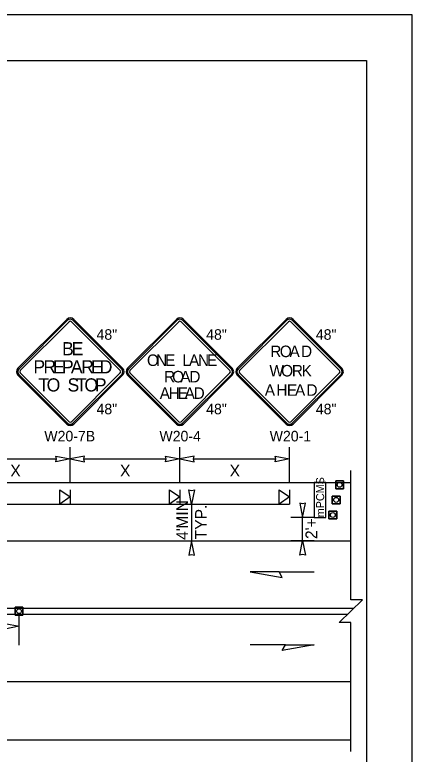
# Model space of a CAD drawing. Extents: x 99999.1 to 100095.7, y 99995 to 100010.7.
# Drawn here: x 100053.34 to 100056.06, y 100005.63 to 100010.69 of the extents above; entities that cross this region are included whole.
import ezdxf

# ---------------------------------------------------------------- set-up
doc = ezdxf.new("R2010")
doc.units = 0
for name, color, linetype in [('RD_ED_ShoulderPavedEdge', 7, 'Continuous'), ('RD_MK_LineDblYellowCenter', 7, 'Continuous'), ('RD_MK_LineEdgeWhite', 7, 'Continuous'), ('SH_GI_PlotLimits', 7, 'Continuous'), ('SH_GI_SheetBorder', 7, 'Continuous'), ('TR_SN_ConstructionSigns', 7, 'Continuous'), ('TR_WZ_PCMS', 7, 'Continuous'), ('TR_WZ_PortableSignMountBlk-Org', 7, 'Continuous'), ('TR_WZ_TrafficCone', 7, 'Continuous'), ('TR_WZ_WorkZoneDetails', 7, 'Continuous'), ('TR_WZ_WorkZoneTextCurrent', 7, 'Continuous')]:
    doc.layers.add(name, color=color, linetype=linetype)

msp = doc.modelspace()

# ---------------------------------------------------------------- linework, layer by layer
at = {"layer": 'RD_ED_ShoulderPavedEdge'}
for p, q in [((100040.1076, 100007.4923), (100055.6424, 100007.4923)), ((100040.1076, 100005.7323), (100055.6424, 100005.7323))]:
    msp.add_line(p, q, dxfattribs=at)
at = {"layer": 'RD_MK_LineDblYellowCenter'}
for p, q in [((100052.2733, 100006.6323), (100055.6631, 100006.6323)), ((100052.2733, 100006.5923), (100055.6218, 100006.5923))]:
    msp.add_line(p, q, dxfattribs=at)
at = {"layer": 'RD_MK_LineEdgeWhite'}
for p, q in [((100040.1076, 100007.0923), (100055.6424, 100007.0923)), ((100040.1076, 100006.1323), (100055.6424, 100006.1323))]:
    msp.add_line(p, q, dxfattribs=at)
at = {"layer": 'SH_GI_PlotLimits'}
msp.add_lwpolyline([(100039.0625, 99999.6875), (100056.0625, 99999.6875), (100056.0625, 100010.6875), (100039.0625, 100010.6875)], close=True, dxfattribs=at)
at = {"layer": 'SH_GI_SheetBorder'}
for p, q in [((100040, 100010.375), (100055.75, 100010.375)), ((100055.75, 100010.375), (100055.75, 100000))]:
    msp.add_line(p, q, dxfattribs=at)
at = {"layer": 'TR_SN_ConstructionSigns'}
for p, q in [((100053.6995, 100008.6062), (100053.3654, 100008.2721)), ((100053.7055, 100008.6002), (100053.3713, 100008.2661)), ((100054.0754, 100008.2661), (100053.7412, 100008.6002)), ((100054.0813, 100008.2721), (100053.7472, 100008.6062)), ((100054.4495, 100008.6062), (100054.1154, 100008.2721)), ((100054.4555, 100008.6002), (100054.1213, 100008.2661)), ((100054.8254, 100008.2661), (100054.4912, 100008.6002)), ((100054.8313, 100008.2721), (100054.4972, 100008.6062)), ((100055.1995, 100008.6062), (100054.8654, 100008.2721)), ((100055.2055, 100008.6002), (100054.8713, 100008.2661)), ((100055.5754, 100008.2661), (100055.2412, 100008.6002)), ((100055.5813, 100008.2721), (100055.2472, 100008.6062)), ((100053.3813, 100008.2561), (100053.7154, 100008.5903)), ((100053.7313, 100008.5903), (100054.0654, 100008.2561)), ((100054.1313, 100008.2561), (100054.4654, 100008.5903)), ((100054.4813, 100008.5903), (100054.8154, 100008.2561)), ((100054.8813, 100008.2561), (100055.2154, 100008.5903)), ((100055.2313, 100008.5903), (100055.5654, 100008.2561)), ((100053.3654, 100008.2243), (100053.6995, 100007.8902)), ((100053.3713, 100008.2303), (100053.7055, 100007.8962)), ((100053.7154, 100007.9061), (100053.3813, 100008.2402)), ((100054.0654, 100008.2402), (100053.7313, 100007.9061)), ((100053.7412, 100007.8962), (100054.0754, 100008.2303)), ((100053.7472, 100007.8902), (100054.0813, 100008.2243)), ((100054.1154, 100008.2243), (100054.4495, 100007.8902)), ((100054.1213, 100008.2303), (100054.4555, 100007.8962)), ((100054.4654, 100007.9061), (100054.1313, 100008.2402)), ((100054.8154, 100008.2402), (100054.4813, 100007.9061)), ((100054.4912, 100007.8962), (100054.8254, 100008.2303)), ((100054.4972, 100007.8902), (100054.8313, 100008.2243)), ((100054.8654, 100008.2243), (100055.1995, 100007.8902)), ((100054.8713, 100008.2303), (100055.2055, 100007.8962)), ((100055.2154, 100007.9061), (100054.8813, 100008.2402)), ((100055.5654, 100008.2402), (100055.2313, 100007.9061)), ((100055.2412, 100007.8962), (100055.5754, 100008.2303)), ((100055.2472, 100007.8902), (100055.5813, 100008.2243))]:
    msp.add_line(p, q, dxfattribs=at)
for centre, radius, start, end in [((100053.7233, 100008.5823), 0.0338, 45, 135), ((100053.7233, 100008.5823), 0.0253, 45, 135), ((100054.4733, 100008.5823), 0.0338, 45, 135), ((100054.4733, 100008.5823), 0.0253, 45, 135), ((100055.2233, 100008.5823), 0.0338, 45, 135), ((100055.2233, 100008.5823), 0.0253, 45, 135), ((100053.7233, 100008.5823), 0.0113, 45, 135), ((100054.4733, 100008.5823), 0.0113, 45, 135), ((100055.2233, 100008.5823), 0.0113, 45, 135), ((100053.3892, 100008.2482), 0.0338, 135, 225), ((100053.3892, 100008.2482), 0.0253, 135, 225), ((100053.3892, 100008.2482), 0.0113, 135, 225), ((100054.0575, 100008.2482), 0.0113, 315, 45), ((100054.0575, 100008.2482), 0.0253, 315, 45), ((100054.0575, 100008.2482), 0.0338, 315, 45), ((100054.1392, 100008.2482), 0.0338, 135, 225), ((100054.1392, 100008.2482), 0.0253, 135, 225), ((100054.1392, 100008.2482), 0.0113, 135, 225), ((100054.8075, 100008.2482), 0.0113, 315, 45), ((100054.8075, 100008.2482), 0.0253, 315, 45), ((100054.8075, 100008.2482), 0.0338, 315, 45), ((100054.8892, 100008.2482), 0.0338, 135, 225), ((100054.8892, 100008.2482), 0.0253, 135, 225), ((100054.8892, 100008.2482), 0.0113, 135, 225), ((100055.5575, 100008.2482), 0.0113, 315, 45), ((100055.5575, 100008.2482), 0.0253, 315, 45), ((100055.5575, 100008.2482), 0.0338, 315, 45), ((100053.7233, 100007.9141), 0.0338, 225, 315), ((100053.7233, 100007.9141), 0.0253, 225, 315), ((100053.7233, 100007.9141), 0.0113, 225, 315), ((100054.4733, 100007.9141), 0.0338, 225, 315), ((100054.4733, 100007.9141), 0.0253, 225, 315), ((100054.4733, 100007.9141), 0.0113, 225, 315), ((100055.2233, 100007.9141), 0.0338, 225, 315), ((100055.2233, 100007.9141), 0.0253, 225, 315), ((100055.2233, 100007.9141), 0.0113, 225, 315)]:
    msp.add_arc(centre, radius, start, end, dxfattribs=at)
at = {"layer": 'TR_WZ_PCMS'}
msp.add_lwpolyline([(100055.4724, 100007.2523), (100055.4724, 100007.4923), (100055.3924, 100007.4923), (100055.3924, 100007.2523)], close=True, dxfattribs=at)
msp.add_lwpolyline([(100055.4724, 100007.2523), (100055.4724, 100007.4923), (100055.3924, 100007.4923), (100055.3924, 100007.2523), (100055.4724, 100007.2523)], dxfattribs=at)
at = {"layer": 'TR_WZ_PortableSignMountBlk-Org'}
for p, q in [((100053.7233, 100007.4422), (100053.7233, 100007.3422)), ((100054.4733, 100007.4422), (100054.4733, 100007.3422)), ((100055.2233, 100007.4422), (100055.2233, 100007.3422))]:
    msp.add_line(p, q, dxfattribs=at)
for points in [[(100053.7233, 100007.3923), (100053.6515, 100007.3422), (100053.6515, 100007.4422)], [(100054.4733, 100007.3923), (100054.4015, 100007.3422), (100054.4015, 100007.4422)], [(100055.2233, 100007.3923), (100055.1515, 100007.3422), (100055.1515, 100007.4422)]]:
    msp.add_lwpolyline(points, close=True, dxfattribs=at)
at = {"layer": 'TR_WZ_TrafficCone'}
for points in [[(100055.5924, 100007.449), (100055.5391, 100007.449), (100055.5391, 100007.5023), (100055.5924, 100007.5023), (100055.5924, 100007.449)], [(100055.5924, 100007.5023), (100055.5391, 100007.5023), (100055.5391, 100007.449), (100055.5924, 100007.449), (100055.5924, 100007.5023)], [(100055.5691, 100007.3457), (100055.5158, 100007.3457), (100055.5158, 100007.399), (100055.5691, 100007.399), (100055.5691, 100007.3457)], [(100055.5691, 100007.399), (100055.5158, 100007.399), (100055.5158, 100007.3457), (100055.5691, 100007.3457), (100055.5691, 100007.399)], [(100055.5458, 100007.2423), (100055.4924, 100007.2423), (100055.4924, 100007.2957), (100055.5458, 100007.2957), (100055.5458, 100007.2423)], [(100055.5458, 100007.2957), (100055.4924, 100007.2957), (100055.4924, 100007.2423), (100055.5458, 100007.2423), (100055.5458, 100007.2957)], [(100053.4, 100006.5857), (100053.3467, 100006.5857), (100053.3467, 100006.639), (100053.4, 100006.639), (100053.4, 100006.5857)], [(100053.4, 100006.639), (100053.3467, 100006.639), (100053.3467, 100006.5857), (100053.4, 100006.5857), (100053.4, 100006.639)]]:
    msp.add_lwpolyline(points, dxfattribs=at)
for centre in [(100055.5658, 100007.4757), (100055.5424, 100007.3723), (100055.5191, 100007.269), (100053.3733, 100006.6123)]:
    msp.add_circle(centre, 0.0167, dxfattribs=at)
at = {"layer": 'TR_WZ_WorkZoneDetails'}
for p, q in [((100053.7233, 100007.4923), (100053.7233, 100007.7323)), ((100054.4733, 100007.4923), (100054.4733, 100007.7323)), ((100055.2233, 100007.4921), (100055.2233, 100007.7323)), ((100053.0671, 100007.6523), (100053.6296, 100007.6523)), ((100053.8171, 100007.6523), (100054.3796, 100007.6523)), ((100054.5671, 100007.6523), (100055.1296, 100007.6523)), ((100052.2233, 100007.3422), (100055.2233, 100007.3422)), ((100054.4733, 100007.3422), (100054.6333, 100007.3422)), ((100054.5533, 100007.3422), (100054.5533, 100007.0923)), ((100055.3924, 100007.2523), (100055.2324, 100007.2523)), ((100055.3124, 100007.0923), (100055.3124, 100007.2523)), ((100054.4733, 100007.0923), (100054.6333, 100007.0923)), ((100055.3924, 100007.0923), (100055.2324, 100007.0923)), ((100055.1513, 100006.8816), (100055.3924, 100006.8816)), ((100053.3733, 100006.379), (100053.3733, 100006.589)), ((100055.1959, 100006.3816), (100054.9548, 100006.3816))]:
    msp.add_line(p, q, dxfattribs=at)
for points in [[(100053.7233, 100007.6523), (100053.6251, 100007.6331), (100053.6296, 100007.6523), (100053.6251, 100007.6716)], [(100053.7233, 100007.6523), (100053.8216, 100007.6331), (100053.8171, 100007.6523), (100053.8216, 100007.6716)], [(100054.4733, 100007.6523), (100054.3751, 100007.6331), (100054.3796, 100007.6523), (100054.3751, 100007.6716)], [(100054.4733, 100007.6523), (100054.5716, 100007.6331), (100054.5671, 100007.6523), (100054.5716, 100007.6716)], [(100055.2233, 100007.6523), (100055.1251, 100007.6331), (100055.1296, 100007.6523), (100055.1251, 100007.6716)], [(100054.5533, 100007.3422), (100054.5341, 100007.4405), (100054.5533, 100007.436), (100054.5726, 100007.4405)], [(100055.3124, 100007.2523), (100055.3317, 100007.3506), (100055.3124, 100007.3461), (100055.2932, 100007.3506)], [(100054.5533, 100007.0923), (100054.5341, 100006.9941), (100054.5533, 100006.9986), (100054.5726, 100006.9941)], [(100055.3124, 100007.0923), (100055.3317, 100006.9941), (100055.3124, 100006.9986), (100055.2932, 100006.9941)], [(100054.9548, 100006.8816), (100055.1736, 100006.843), (100055.1513, 100006.8816)], [(100053.3733, 100006.509), (100053.2751, 100006.4897), (100053.2796, 100006.509), (100053.2751, 100006.5283)], [(100055.3924, 100006.3816), (100055.1736, 100006.343), (100055.1959, 100006.3816)]]:
    msp.add_lwpolyline(points, close=True, dxfattribs=at)
msp.add_lwpolyline([(100055.6424, 100005.6523), (100055.6424, 100006.5349), (100055.5624, 100006.5349), (100055.7225, 100006.6898), (100055.6424, 100006.6898), (100055.6424, 100007.5723)], dxfattribs=at)

# ---------------------------------------------------------------- texts
at = {"layer": 'TR_SN_ConstructionSigns'}
for s, p in [('48"', (100053.9031, 100008.4667)), ('48"', (100054.6531, 100008.4667)), ('48"', (100055.4031, 100008.4667)), ('48"', (100053.9031, 100007.9576)), ('48"', (100054.6531, 100007.9576)), ('48"', (100055.4031, 100007.9576)), ('W20-7B', (100053.546, 100007.7723)), ('W20-4', (100054.3334, 100007.7723)), ('W20-1', (100055.0875, 100007.7723))]:
    msp.add_text(s, height=0.072, rotation=360, dxfattribs=at).set_placement(p)
for s, height, p in [('B', 0.09, (100053.6675, 100008.3607)), ('E', 0.09, (100053.7332, 100008.3607)), ('R', 0.0788, (100055.0914, 100008.348)), ('O', 0.0788, (100055.1568, 100008.348)), ('A', 0.0788, (100055.223, 100008.348)), ('D', 0.0788, (100055.3017, 100008.348)), ('O', 0.0787, (100054.2481, 100008.2876)), ('N', 0.0787, (100054.3103, 100008.2876)), ('E', 0.0787, (100054.3718, 100008.2876)), ('L', 0.0787, (100054.4907, 100008.2876)), ('A', 0.0787, (100054.5356, 100008.2876)), ('N', 0.0787, (100054.597, 100008.2876)), ('E', 0.0787, (100054.6584, 100008.2876)), ('P', 0.09, (100053.4713, 100008.2369)), ('R', 0.09, (100053.5397, 100008.2369)), ('E', 0.09, (100053.6054, 100008.2369)), ('P', 0.09, (100053.6666, 100008.2369)), ('A', 0.09, (100053.7278, 100008.2369)), ('R', 0.09, (100053.798, 100008.2369)), ('E', 0.09, (100053.8637, 100008.2369)), ('D', 0.09, (100053.9249, 100008.2369)), ('W', 0.0788, (100055.0855, 100008.2158)), ('O', 0.0788, (100055.1659, 100008.2158)), ('R', 0.0788, (100055.2391, 100008.2158)), ('K', 0.0788, (100055.306, 100008.2158)), ('R', 0.0787, (100054.3647, 100008.1751)), ('O', 0.0787, (100054.4206, 100008.1751)), ('A', 0.0787, (100054.4765, 100008.1751)), ('D', 0.0787, (100054.5379, 100008.1751)), ('T', 0.09, (100053.5051, 100008.1132)), ('O', 0.09, (100053.5618, 100008.1132)), ('S', 0.09, (100053.7049, 100008.1132)), ('T', 0.09, (100053.7634, 100008.1132)), ('O', 0.09, (100053.8201, 100008.1132)), ('P', 0.09, (100053.8912, 100008.1132)), ('A', 0.0788, (100055.054, 100008.0837)), ('H', 0.0788, (100055.1328, 100008.0837)), ('E', 0.0788, (100055.2052, 100008.0837)), ('A', 0.0788, (100055.2604, 100008.0837)), ('D', 0.0788, (100055.3391, 100008.0837)), ('A', 0.0787, (100054.3355, 100008.0626)), ('H', 0.0787, (100054.397, 100008.0626)), ('E', 0.0787, (100054.4584, 100008.0626)), ('A', 0.0787, (100054.5056, 100008.0626)), ('D', 0.0787, (100054.5671, 100008.0626))]:
    msp.add_text(s, height=height, dxfattribs=at).set_placement(p)
at = {"layer": 'TR_WZ_PCMS'}
msp.add_text('mPCMS', height=0.055, rotation=90, dxfattribs=at).set_placement((100055.4599, 100007.2538))
at = {"layer": 'TR_WZ_WorkZoneTextCurrent'}
for p in [(100053.3136, 100007.5323), (100054.0636, 100007.5323), (100054.8136, 100007.5323)]:
    msp.add_text('X', height=0.08, dxfattribs=at).set_placement(p)
for s, p in [('MIN', (100054.5293, 100007.1754)), ('TYP.', (100054.6573, 100007.1026)), ("2'+", (100055.4124, 100007.1046)), ("4'", (100054.5293, 100007.0989))]:
    msp.add_text(s, height=0.08, rotation=90, dxfattribs=at).set_placement(p)

doc.saveas('drawing.dxf')
